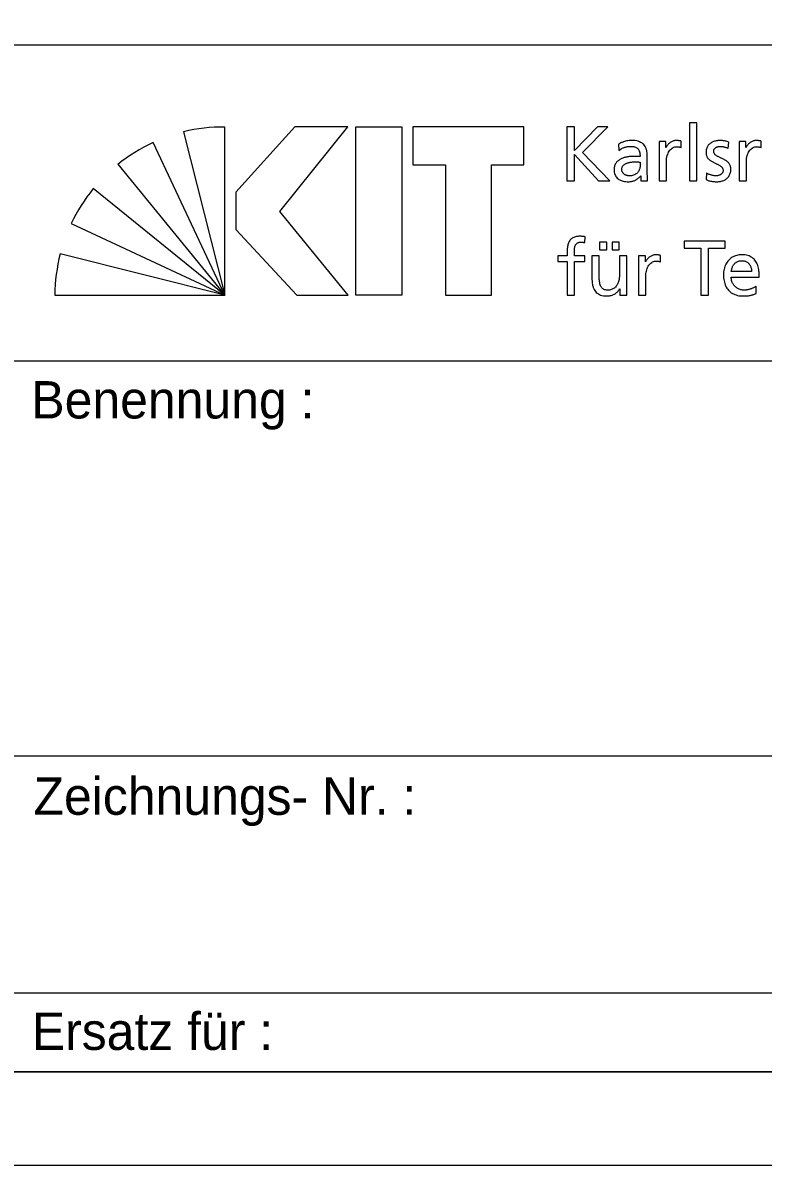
# Model space of a CAD drawing. Extents: x 0 to 297, y 0 to 210.
# Drawn here: x 252.83 to 272.66, y 0 to 30.58 of the extents above; entities that cross this region are included whole.
import ezdxf

# ---------------------------------------------------------------- set-up
doc = ezdxf.new("R2010")
doc.units = 0
doc.layers.add('90_Plankopf', color=7, linetype='Continuous')

msp = doc.modelspace()

# ---------------------------------------------------------------- linework, layer by layer
at = {"layer": '90_Plankopf'}
for p, q in [((205.56, 29.995), (294.5, 29.995)), ((205.56, 29.995), (294.5, 29.995)), ((257.137, 27.666), (258.24, 23.293)), ((258.24, 23.293), (258.24, 27.792)), ((267.405, 27.793), (267.405, 26.353)), ((258.24, 23.293), (256.317, 27.376)), ((268.79, 27.331), (268.8, 27.166)), ((270.463, 27.242), (270.463, 27.416)), ((271.728, 27.22), (271.745, 27.389)), ((272.606, 27.242), (272.606, 27.416)), ((269.559, 26.559), (269.559, 26.995)), ((255.372, 26.793), (258.24, 23.293)), ((269.365, 26.854), (269.365, 26.761)), ((267.405, 26.353), (267.611, 26.353)), ((268.253, 26.353), (268.554, 26.353)), ((271.149, 26.559), (271.138, 26.386)), ((258.24, 23.293), (254.717, 26.143)), ((254.12, 25.207), (258.24, 23.293)), ((267.887, 24.696), (267.895, 24.853)), ((258.24, 23.293), (253.829, 24.394)), ((269.913, 24.182), (269.913, 24.356)), ((272.353, 23.92), (271.808, 23.92)), ((271.808, 23.776), (272.559, 23.776)), ((253.682, 23.293), (258.24, 23.293)), ((272.479, 23.337), (272.479, 23.53)), ((252.501, 21.535), (294.5, 21.535)), ((252.501, 10.96), (294.5, 10.96)), ((252.501, 4.615), (294.5, 4.615)), ((294.5, 2.5), (205.56, 2.5)), ((211.4, 2.5), (294.5, 2.5)), ((211.4, 2.5), (294.5, 2.5))]:
    msp.add_line(p, q, dxfattribs=at)
for points in [[(0, 0), (297, 0), (297, 210), (0, 210)], [(12.5, 207.5), (294.5, 207.5), (294.5, 2.5), (12.5, 2.5)], [(261.533, 27.793), (260.118, 27.793), (258.536, 26.049), (258.536, 25.046), (260.169, 23.293), (261.542, 23.293), (259.711, 25.531)], [(262.985, 27.793), (262.985, 23.293), (261.751, 23.293), (261.751, 27.793)], [(263.281, 27.793), (263.281, 26.78), (264.151, 26.78), (264.151, 23.293), (265.385, 23.293), (265.385, 26.78), (266.255, 26.78), (266.255, 27.793)]]:
    msp.add_lwpolyline(points, close=True, dxfattribs=at)
for points in [[(270.69, 26.353), (270.884, 26.353), (270.884, 27.9), (270.69, 27.9), (270.69, 26.353)], [(268.554, 26.353), (267.824, 27.112), (268.5, 27.793), (268.226, 27.793), (267.611, 27.16), (267.611, 27.793), (267.405, 27.793)], [(270.061, 27.242), (270.057, 27.242), (270.057, 27.405), (269.875, 27.405), (269.875, 26.353), (270.069, 26.353), (270.069, 26.832)], [(272.203, 27.242), (272.199, 27.242), (272.199, 27.405), (272.018, 27.405), (272.018, 26.353), (272.212, 26.353), (272.212, 26.832)], [(267.611, 26.353), (267.611, 27.059), (268.253, 26.353)], [(269.382, 26.489), (269.386, 26.489), (269.386, 26.353), (269.567, 26.353)], [(268.277, 24.713), (268.277, 24.506), (268.471, 24.506), (268.471, 24.713), (268.277, 24.713)], [(268.615, 24.713), (268.615, 24.506), (268.809, 24.506), (268.809, 24.713), (268.615, 24.713)], [(270.995, 23.293), (271.201, 23.293), (271.201, 24.552), (271.649, 24.552), (271.649, 24.733), (270.547, 24.733), (270.547, 24.552), (270.995, 24.552), (270.995, 23.293)], [(267.412, 24.443), (267.412, 24.346), (267.165, 24.346), (267.165, 24.189), (267.412, 24.189), (267.412, 23.293), (267.606, 23.293), (267.606, 24.189), (267.885, 24.189), (267.885, 24.346), (267.606, 24.346), (267.606, 24.459)], [(268.271, 23.801), (268.271, 24.346), (268.077, 24.346), (268.077, 23.72)], [(269.007, 23.293), (269.007, 24.346), (268.813, 24.346), (268.813, 23.859)], [(269.511, 24.182), (269.507, 24.182), (269.507, 24.346), (269.325, 24.346), (269.325, 23.293), (269.519, 23.293), (269.519, 23.772)], [(268.816, 23.46), (268.82, 23.46), (268.82, 23.293), (269.007, 23.293)]]:
    msp.add_lwpolyline(points, dxfattribs=at)
for centre, start, end in [((258.224, 23.028), 89.8053, 103.1895), ((258.331, 23.059), 115.0126, 128.3968), ((258.408, 23.131), 140.7898, 154.174), ((258.446, 23.219), 165.7222, 179.1064)]:
    msp.add_arc(centre, 4.764, start, end, dxfattribs=at)
for points in [[(269.559, 26.995), (269.56, 27.09), (269.545, 27.17), (269.517, 27.235), (269.488, 27.3), (269.442, 27.348), (269.38, 27.381), (269.317, 27.413), (269.236, 27.43), (269.136, 27.43), (269.069, 27.43), (269.007, 27.42), (268.949, 27.402), (268.891, 27.384), (268.838, 27.361), (268.79, 27.331)], [(268.8, 27.166), (268.826, 27.188), (268.856, 27.207), (268.89, 27.223), (268.923, 27.239), (268.958, 27.251), (268.995, 27.26), (269.032, 27.269), (269.068, 27.273), (269.105, 27.273), (269.17, 27.273), (269.221, 27.263), (269.259, 27.243), (269.297, 27.222), (269.324, 27.191), (269.341, 27.151), (269.358, 27.11), (269.365, 27.059), (269.365, 26.999)], [(270.463, 27.416), (270.45, 27.418), (270.437, 27.421), (270.425, 27.423), (270.412, 27.425), (270.399, 27.427), (270.385, 27.428), (270.371, 27.429), (270.354, 27.43), (270.335, 27.43), (270.298, 27.43), (270.261, 27.422), (270.226, 27.406), (270.191, 27.39), (270.159, 27.368), (270.13, 27.339), (270.101, 27.311), (270.078, 27.279), (270.061, 27.242)], [(270.069, 26.832), (270.069, 26.92), (270.081, 26.996), (270.105, 27.06), (270.129, 27.124), (270.162, 27.174), (270.205, 27.208), (270.247, 27.243), (270.298, 27.26), (270.356, 27.261), (270.373, 27.261), (270.39, 27.26), (270.409, 27.257), (270.427, 27.254), (270.445, 27.249), (270.463, 27.242)], [(271.745, 27.389), (271.707, 27.4), (271.669, 27.41), (271.63, 27.418), (271.591, 27.426), (271.549, 27.43), (271.504, 27.43), (271.451, 27.43), (271.403, 27.423), (271.358, 27.41), (271.313, 27.397), (271.274, 27.377), (271.24, 27.35), (271.206, 27.323), (271.18, 27.29), (271.161, 27.249), (271.142, 27.208), (271.132, 27.161), (271.132, 27.106), (271.132, 27.064), (271.141, 27.028), (271.158, 26.997), (271.174, 26.966), (271.195, 26.94), (271.223, 26.917), (271.25, 26.895), (271.279, 26.875), (271.312, 26.857), (271.344, 26.84), (271.376, 26.824), (271.409, 26.809), (271.441, 26.793), (271.471, 26.777), (271.498, 26.761), (271.525, 26.745), (271.547, 26.727), (271.563, 26.706), (271.579, 26.686), (271.588, 26.663), (271.588, 26.636), (271.588, 26.607), (271.582, 26.584), (271.57, 26.564), (271.558, 26.545), (271.542, 26.529), (271.522, 26.518), (271.503, 26.506), (271.482, 26.498), (271.459, 26.493), (271.435, 26.487), (271.412, 26.485), (271.39, 26.485), (271.371, 26.485), (271.347, 26.488), (271.32, 26.493), (271.292, 26.499), (271.263, 26.507), (271.233, 26.518), (271.203, 26.529), (271.175, 26.543), (271.149, 26.559)], [(271.138, 26.386), (271.183, 26.363), (271.23, 26.347), (271.279, 26.339), (271.328, 26.331), (271.377, 26.327), (271.427, 26.328), (271.475, 26.328), (271.52, 26.335), (271.564, 26.348), (271.607, 26.361), (271.647, 26.381), (271.681, 26.408), (271.716, 26.435), (271.743, 26.469), (271.764, 26.51), (271.784, 26.551), (271.794, 26.6), (271.795, 26.656), (271.794, 26.704), (271.786, 26.745), (271.769, 26.778), (271.753, 26.811), (271.731, 26.84), (271.704, 26.863), (271.677, 26.886), (271.647, 26.906), (271.615, 26.922), (271.583, 26.939), (271.55, 26.954), (271.518, 26.968), (271.486, 26.983), (271.456, 26.998), (271.429, 27.013), (271.402, 27.029), (271.38, 27.047), (271.364, 27.068), (271.347, 27.089), (271.339, 27.115), (271.338, 27.145), (271.339, 27.174), (271.348, 27.198), (271.365, 27.217), (271.382, 27.236), (271.404, 27.25), (271.432, 27.259), (271.46, 27.269), (271.491, 27.273), (271.524, 27.273), (271.536, 27.273), (271.551, 27.271), (271.569, 27.269), (271.588, 27.266), (271.607, 27.261), (271.627, 27.256), (271.648, 27.251), (271.667, 27.246), (271.685, 27.239), (271.703, 27.233), (271.717, 27.226), (271.728, 27.22)], [(272.606, 27.416), (272.592, 27.418), (272.579, 27.421), (272.567, 27.423), (272.555, 27.425), (272.541, 27.427), (272.527, 27.428), (272.513, 27.429), (272.497, 27.43), (272.478, 27.43), (272.44, 27.43), (272.404, 27.422), (272.368, 27.406), (272.333, 27.39), (272.301, 27.368), (272.273, 27.339), (272.244, 27.311), (272.221, 27.279), (272.203, 27.242)], [(272.212, 26.832), (272.212, 26.92), (272.224, 26.996), (272.247, 27.06), (272.271, 27.124), (272.304, 27.174), (272.347, 27.208), (272.39, 27.243), (272.44, 27.26), (272.498, 27.261), (272.515, 27.261), (272.533, 27.26), (272.551, 27.257), (272.57, 27.254), (272.588, 27.249), (272.606, 27.242)], [(269.365, 26.999), (269.34, 27), (269.317, 27.001), (269.295, 27.001), (269.273, 27.002), (269.251, 27.003), (269.229, 27.003), (269.208, 27.003), (269.184, 27.003), (269.159, 27.003), (269.118, 27.003), (269.076, 26.999), (269.031, 26.992), (268.987, 26.985), (268.943, 26.973), (268.9, 26.957), (268.858, 26.941), (268.819, 26.919), (268.784, 26.892), (268.75, 26.866), (268.722, 26.833), (268.701, 26.794), (268.681, 26.755), (268.671, 26.709), (268.67, 26.656), (268.671, 26.58), (268.687, 26.518), (268.719, 26.469), (268.752, 26.421), (268.797, 26.385), (268.855, 26.362), (268.913, 26.339), (268.979, 26.328), (269.056, 26.328), (269.1, 26.328), (269.14, 26.334), (269.175, 26.344), (269.21, 26.355), (269.241, 26.368), (269.268, 26.384), (269.295, 26.401), (269.318, 26.419), (269.337, 26.437), (269.355, 26.455), (269.37, 26.472), (269.382, 26.489)], [(269.365, 26.761), (269.365, 26.709), (269.354, 26.661), (269.332, 26.62), (269.31, 26.578), (269.277, 26.546), (269.233, 26.522), (269.19, 26.498), (269.136, 26.485), (269.072, 26.485), (269.05, 26.485), (269.027, 26.489), (269.004, 26.496), (268.981, 26.503), (268.96, 26.514), (268.941, 26.529), (268.922, 26.543), (268.906, 26.561), (268.894, 26.582), (268.883, 26.604), (268.877, 26.628), (268.876, 26.656), (268.877, 26.693), (268.886, 26.724), (268.904, 26.749), (268.922, 26.773), (268.946, 26.793), (268.975, 26.807), (269.003, 26.822), (269.034, 26.833), (269.067, 26.841), (269.1, 26.848), (269.132, 26.853), (269.163, 26.855), (269.194, 26.858), (269.22, 26.859), (269.241, 26.858), (269.262, 26.858), (269.283, 26.858), (269.303, 26.856), (269.324, 26.855), (269.345, 26.855), (269.365, 26.854)], [(269.567, 26.353), (269.566, 26.363), (269.565, 26.377), (269.563, 26.393), (269.562, 26.411), (269.561, 26.433), (269.561, 26.46), (269.56, 26.486), (269.559, 26.52), (269.559, 26.559)], [(267.895, 24.853), (267.875, 24.856), (267.855, 24.859), (267.834, 24.862), (267.812, 24.864), (267.79, 24.866), (267.765, 24.866), (267.694, 24.865), (267.635, 24.855), (267.589, 24.836), (267.543, 24.816), (267.507, 24.787), (267.481, 24.75), (267.455, 24.713), (267.437, 24.668), (267.427, 24.616), (267.417, 24.565), (267.412, 24.507), (267.412, 24.443)], [(267.606, 24.459), (267.606, 24.495), (267.608, 24.528), (267.612, 24.558), (267.616, 24.588), (267.625, 24.615), (267.637, 24.637), (267.65, 24.66), (267.669, 24.677), (267.694, 24.69), (267.719, 24.702), (267.752, 24.709), (267.794, 24.709), (267.811, 24.709), (267.828, 24.708), (267.844, 24.706), (267.861, 24.703), (267.875, 24.7), (267.887, 24.696)], [(269.913, 24.356), (269.9, 24.359), (269.887, 24.361), (269.875, 24.363), (269.863, 24.365), (269.849, 24.367), (269.835, 24.368), (269.821, 24.37), (269.804, 24.37), (269.786, 24.37), (269.748, 24.37), (269.712, 24.362), (269.676, 24.346), (269.641, 24.33), (269.609, 24.308), (269.581, 24.28), (269.552, 24.252), (269.529, 24.219), (269.511, 24.182)], [(269.519, 23.772), (269.52, 23.86), (269.532, 23.937), (269.555, 24.001), (269.579, 24.065), (269.612, 24.114), (269.655, 24.148), (269.698, 24.183), (269.748, 24.201), (269.806, 24.201), (269.823, 24.201), (269.841, 24.2), (269.859, 24.197), (269.878, 24.195), (269.896, 24.19), (269.913, 24.182)], [(272.559, 23.776), (272.56, 23.861), (272.552, 23.94), (272.536, 24.012), (272.52, 24.084), (272.495, 24.146), (272.459, 24.2), (272.423, 24.254), (272.375, 24.295), (272.315, 24.325), (272.256, 24.355), (272.182, 24.37), (272.095, 24.37), (272.02, 24.37), (271.953, 24.357), (271.892, 24.331), (271.832, 24.305), (271.78, 24.269), (271.737, 24.221), (271.694, 24.174), (271.66, 24.118), (271.637, 24.052), (271.614, 23.988), (271.602, 23.916), (271.602, 23.838), (271.602, 23.752), (271.613, 23.674), (271.634, 23.604), (271.656, 23.535), (271.69, 23.475), (271.734, 23.425), (271.779, 23.375), (271.835, 23.336), (271.904, 23.309), (271.973, 23.282), (272.053, 23.269), (272.147, 23.268), (272.204, 23.269), (272.253, 23.273), (272.293, 23.28), (272.334, 23.288), (272.369, 23.297), (272.398, 23.307), (272.428, 23.317), (272.454, 23.327), (272.479, 23.337)], [(271.808, 23.92), (271.812, 23.955), (271.82, 23.989), (271.832, 24.024), (271.844, 24.058), (271.861, 24.089), (271.884, 24.118), (271.906, 24.147), (271.934, 24.17), (271.969, 24.187), (272.003, 24.204), (272.043, 24.213), (272.091, 24.213), (272.133, 24.213), (272.17, 24.206), (272.202, 24.19), (272.235, 24.175), (272.262, 24.154), (272.285, 24.127), (272.307, 24.101), (272.324, 24.069), (272.335, 24.034), (272.347, 23.999), (272.353, 23.961), (272.353, 23.92)], [(268.813, 23.859), (268.813, 23.794), (268.807, 23.736), (268.795, 23.683), (268.782, 23.63), (268.763, 23.584), (268.736, 23.546), (268.71, 23.507), (268.677, 23.478), (268.637, 23.457), (268.596, 23.436), (268.549, 23.426), (268.494, 23.425), (268.438, 23.429), (268.393, 23.444), (268.361, 23.473), (268.328, 23.501), (268.305, 23.542), (268.291, 23.597), (268.277, 23.651), (268.271, 23.719), (268.271, 23.801)], [(268.077, 23.72), (268.077, 23.626), (268.091, 23.545), (268.118, 23.478), (268.146, 23.41), (268.19, 23.359), (268.248, 23.323), (268.306, 23.287), (268.38, 23.269), (268.471, 23.268), (268.52, 23.269), (268.568, 23.276), (268.613, 23.291), (268.658, 23.307), (268.698, 23.329), (268.733, 23.357), (268.768, 23.386), (268.796, 23.42), (268.816, 23.46)], [(272.479, 23.53), (272.467, 23.521), (272.449, 23.51), (272.426, 23.497), (272.403, 23.485), (272.377, 23.474), (272.347, 23.463), (272.317, 23.452), (272.286, 23.443), (272.253, 23.436), (272.22, 23.429), (272.187, 23.426), (272.155, 23.425), (272.108, 23.426), (272.065, 23.434), (272.023, 23.451), (271.982, 23.468), (271.945, 23.492), (271.913, 23.523), (271.88, 23.554), (271.855, 23.59), (271.836, 23.633), (271.818, 23.676), (271.809, 23.724), (271.808, 23.776)]]:
    msp.add_open_spline(points, degree=3, dxfattribs=at)

# ---------------------------------------------------------------- texts
for s, p in [('Benennung :', (253.057, 19.989)), ('Zeichnungs- Nr. :', (253.114, 9.379)), ('Ersatz für :', (253.069, 3.084))]:
    msp.add_text(s, height=1, dxfattribs=at).set_placement(p)

doc.saveas('drawing.dxf')
